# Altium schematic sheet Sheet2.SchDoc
size B
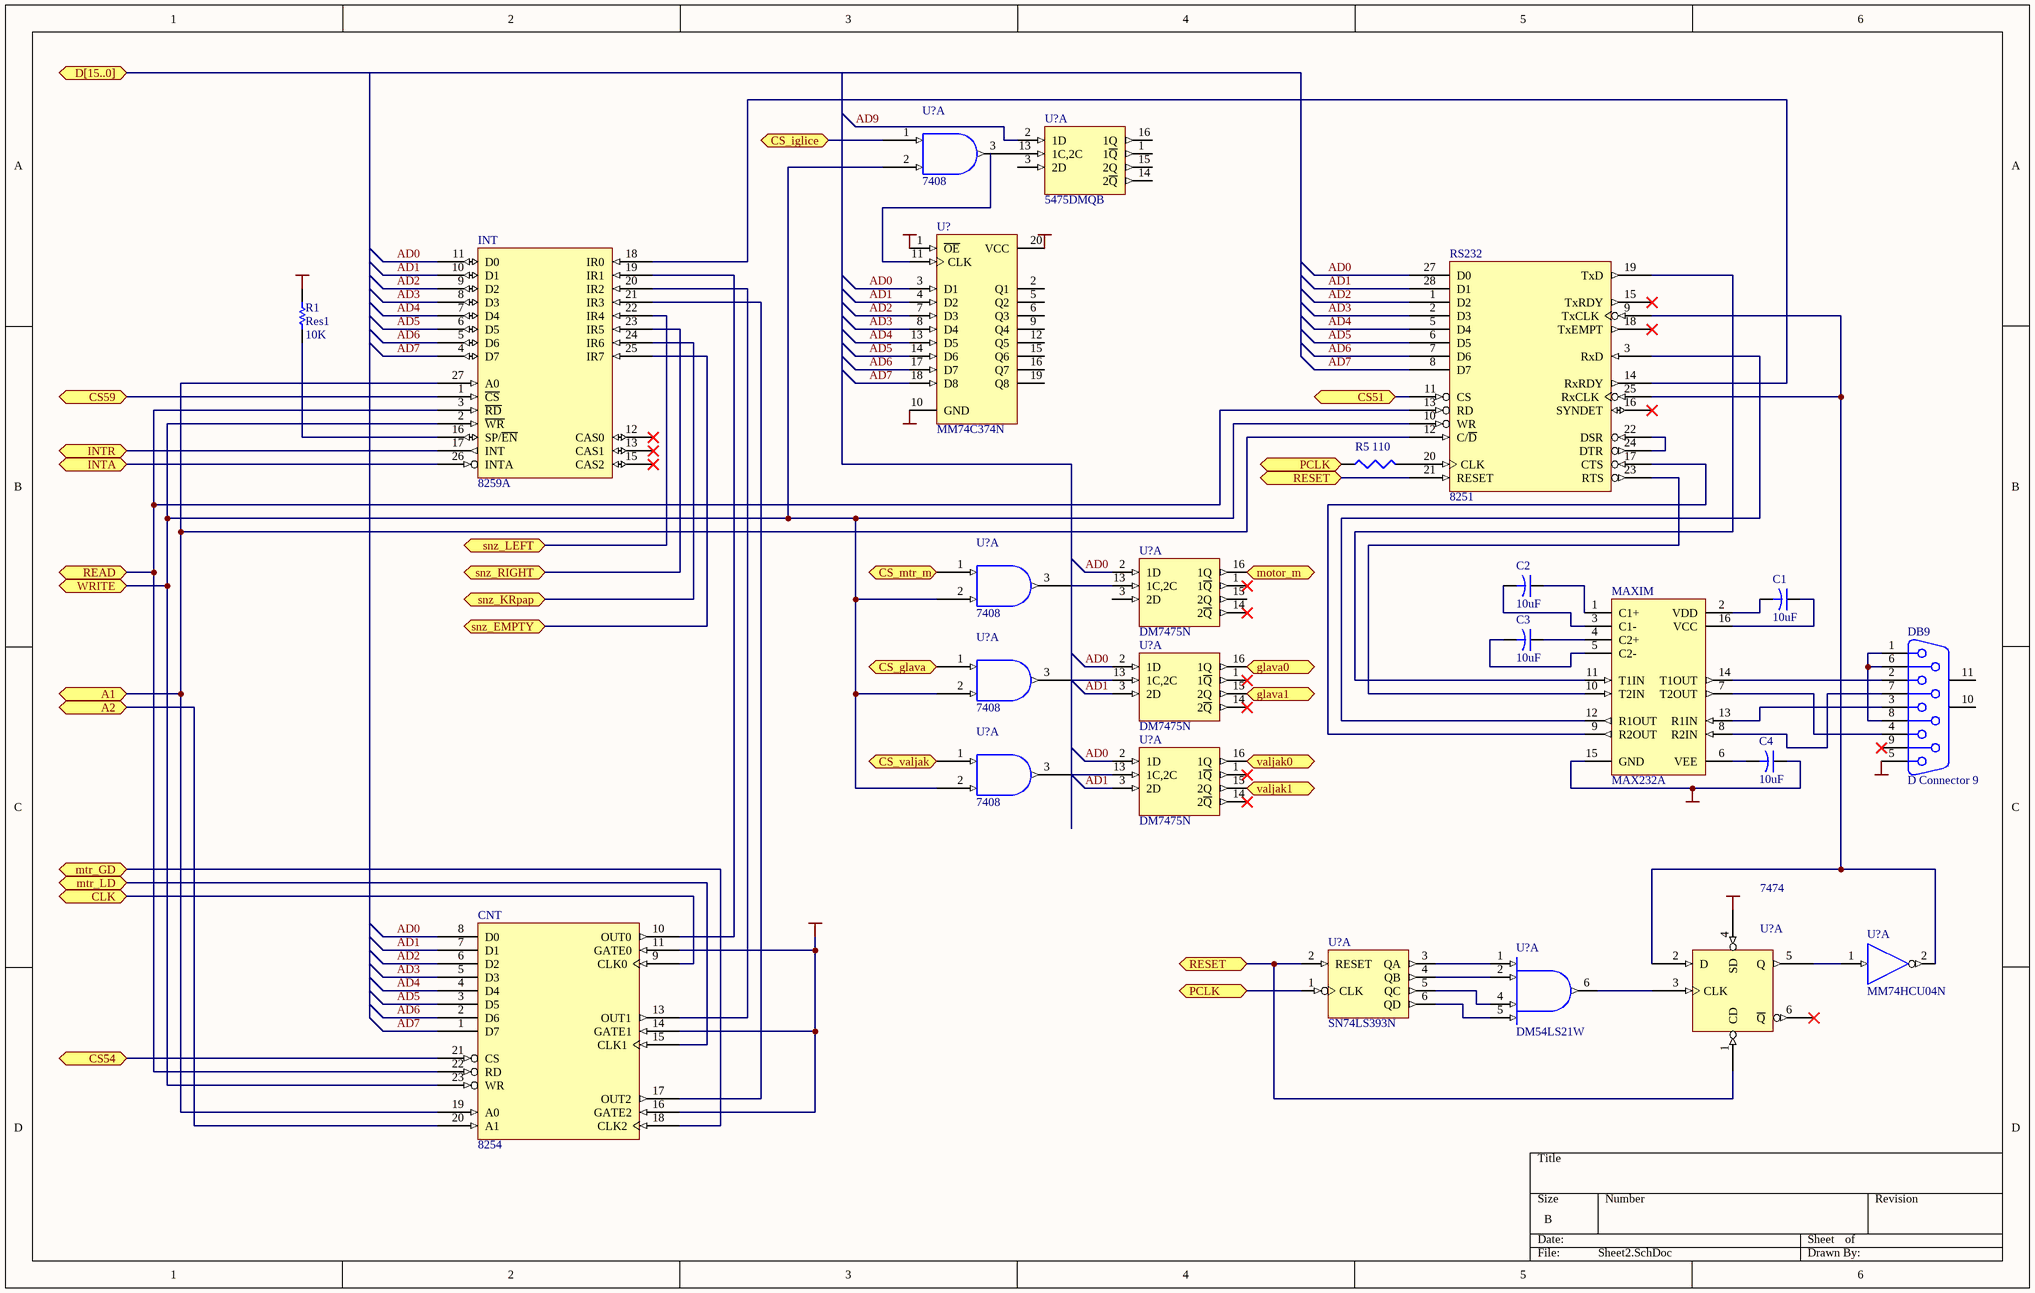
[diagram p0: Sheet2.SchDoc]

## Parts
(Parts that share a designator on the sheet are numbered #1, #2 ... from top to bottom, then left to right.)
?  R5 110
C1  10uF  [CAPR5-4X5]
C2  10uF  [CAPR5-4X5]
C3  10uF  [CAPR5-4X5]
C4  10uF  [CAPR5-4X5]
CNT  8254  [DIP24]
DB9  D Connector 9  [DSUB1.385-2H9]
INT  8259A
MAXIM  MAX232A  [SO-G16/G6.9]
R1  Res1  value 10K  [AXIAL-0.3]
RS232  8251  [DIP28]
U?#1  7408  [DIP14]  (part A of 4)
U?#2  5475DMQB  [DIP-16]  (part A of 2)
U?#3  MM74C374N  [DIP-20/E5.3]
U?#4  7408  [DIP14]  (part A of 4)
U?#5  DM7475N  [DIP-16]  (part A of 2)
U?#6  7408  [DIP14]  (part A of 4)
U?#7  DM7475N  [DIP-16]  (part A of 2)
U?#8  7408  [DIP14]  (part A of 4)
U?#9  DM7475N  [DIP-16]  (part A of 2)
U?#10  MM74HCU04N  [DIP-14/D19.7]  (part A of 6)
U?#11  SN74LS393N  [DIP-14/D19.7]  (part A of 2)
U?#12  7474  [DIP14]  (part A of 2)
U?#13  DM54LS21W  [CDFP-G14/C9.5]  (part A of 2)

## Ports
A1, A2, CLK, CS51, CS54, CS59, CS_glava, CS_iglice, CS_mtr_m, CS_valjak, D[15..0], glava0, glava1, INTA, INTR, motor_m, mtr_GD, mtr_LD, PCLK, READ, RESET, snz_EMPTY, snz_KRpap, snz_LEFT, snz_RIGHT, valjak0, valjak1, WRITE

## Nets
GND: C4.1 CNT.12(GND) DB9.5 INT.14(GND) MAXIM.15(GND) RS232.4(GND) U?#1.7(GND) U?#2.12(GND) U?#3.1(~{OE}) U?#3.10(GND) U?#4.7(GND) U?#5.12(GND) U?#6.7(GND) U?#7.12(GND) U?#8.7(GND) U?#9.12(GND) U?#10.7(GND) U?#11.7(GND) U?#12.7(GND) U?#13.7(GND)
VCC: CNT.11(GATE0) CNT.14(GATE1) CNT.16(GATE2) CNT.24(VCC) INT.28(VCC) R1.2 RS232.26(VCC) U?#1.14(VCC) U?#2.5(VCC) U?#3.20(VCC) U?#4.14(VCC) U?#5.5(VCC) U?#6.14(VCC) U?#7.5(VCC) U?#8.14(VCC) U?#9.5(VCC) U?#10.14(VCC) U?#12.4(SD) U?#12.14(VCC) U?#13.14(VCC)
VDD: U?#11.14(VDD)
A1: CNT.19(A0) INT.27(A0) RS232.12(C/~{D}) ; port A1
A2: CNT.20(A1) ; port A2
AD0: CNT.8(D0) INT.11(D0) RS232.27(D0) U?#3.3(D1) U?#5.2(1D) U?#7.2(1D) U?#9.2(1D)
AD1: CNT.7(D1) INT.10(D1) RS232.28(D1) U?#3.4(D2) U?#7.3(2D) U?#9.3(2D)
AD2: CNT.6(D2) INT.9(D2) RS232.1(D2) U?#3.7(D3)
AD3: CNT.5(D3) INT.8(D3) RS232.2(D3) U?#3.8(D4)
AD4: CNT.4(D4) INT.7(D4) RS232.5(D4) U?#3.13(D5)
AD5: CNT.3(D5) INT.6(D5) RS232.6(D5) U?#3.14(D6)
AD6: CNT.2(D6) INT.5(D6) RS232.7(D6) U?#3.17(D7)
AD7: CNT.1(D7) INT.4(D7) RS232.8(D7) U?#3.18(D8)
AD9: U?#2.2(1D)
CLK: CNT.9(CLK0) ; port CLK
CS51: RS232.11(CS) ; port CS51
CS54: CNT.21(CS) ; port CS54
CS59: INT.1(~{CS}) ; port CS59
CS_glava: U?#6.1 ; port CS_glava
CS_iglice: U?#1.1 ; port CS_iglice
CS_mtr_m: U?#4.1 ; port CS_mtr_m
CS_valjak: U?#8.1 ; port CS_valjak
glava0: U?#7.16(1Q) ; port glava0
glava1: U?#7.15(2Q) ; port glava1
INTA: INT.26(INTA) ; port INTA
INTR: INT.17(INT) ; port INTR
motor_m: U?#5.16(1Q) ; port motor_m
mtr_GD: CNT.18(CLK2) ; port mtr_GD
mtr_LD: CNT.15(CLK1) ; port mtr_LD
PCLK: ?.1 U?#11.1(CLK) ; port PCLK
READ: CNT.22(RD) INT.3(~{RD}) RS232.13(RD) ; port READ
RESET: RS232.21(RESET) U?#11.2(RESET) U?#12.1(CD) ; port RESET
snz_EMPTY: INT.25(IR7) ; port snz_EMPTY
snz_KRpap: INT.24(IR6) ; port snz_KRpap
snz_LEFT: INT.22(IR4) ; port snz_LEFT
snz_RIGHT: INT.23(IR5) ; port snz_RIGHT
valjak0: U?#9.16(1Q) ; port valjak0
valjak1: U?#9.15(2Q) ; port valjak1
WRITE: CNT.23(WR) INT.2(~{WR}) RS232.10(WR) U?#1.2 U?#4.2 U?#6.2 U?#8.2 ; port WRITE
Net?_2: ?.2 RS232.20(CLK)
NetC1_1: C1.1 MAXIM.16(VCC)
NetC1_2: C1.2 MAXIM.2(VDD)
NetC2_1: C2.1 MAXIM.1(C1+)
NetC2_2: C2.2 MAXIM.3(C1-)
NetC3_1: C3.1 MAXIM.4(C2+)
NetC3_2: C3.2 MAXIM.5(C2-)
NetC4_2: C4.2 MAXIM.6(VEE)
NetCNT_10: CNT.10(OUT0) INT.19(IR1)
NetCNT_13: CNT.13(OUT1) INT.20(IR2)
NetCNT_17: CNT.17(OUT2) INT.21(IR3)
NetDB9_1: DB9.1 DB9.6 DB9.8
NetDB9_2: DB9.2 MAXIM.14(T1OUT)
NetDB9_3: DB9.3 MAXIM.13(R1IN)
NetDB9_4: DB9.4 MAXIM.7(T2OUT)
NetDB9_7: DB9.7 MAXIM.8(R2IN)
NetINT_16: INT.16(SP/~{EN}) R1.1
NetINT_18: INT.18(IR0) RS232.14(RxRDY)
NetMAXIM_9: MAXIM.9(R2OUT) RS232.17(CTS)
NetMAXIM_10: MAXIM.10(T2IN) RS232.23(RTS)
NetMAXIM_11: MAXIM.11(T1IN) RS232.19(TxD)
NetMAXIM_12: MAXIM.12(R1OUT) RS232.3(RxD)
NetRS232_9: RS232.9(TxCLK) RS232.25(RxCLK) U?#10.2(Y) U?#12.2(D)
NetRS232_22: RS232.22(DSR) RS232.24(DTR)
NetU?#1_3: U?#1.3 U?#2.13(1C,2C)
NetU?#4_3: U?#4.3 U?#5.13(1C,2C)
NetU?#6_3: U?#6.3 U?#7.13(1C,2C)
NetU?#8_3: U?#8.3 U?#9.13(1C,2C)
NetU?#10_1: U?#10.1(A) U?#12.5(Q)
NetU?#11_3: U?#11.3(QA) U?#13.1(A)
NetU?#11_4: U?#11.4(QB) U?#13.2(B)
NetU?#11_5: U?#11.5(QC) U?#13.4(C)
NetU?#11_6: U?#11.6(QD) U?#13.5(D)
NetU?#12_3: U?#12.3(CLK) U?#13.6(Y)

Not connected (* = marked no-connect by the designer): DB9 9* 10(MH1) 11(MH2); INT 12(CAS0)* 13(CAS1)* 15(CAS2)*; RS232 15(TxRDY)* 16(SYNDET)* 18(TxEMPT)*; U?#2 1(1~{Q}) 3(2D) 14(2~{Q}) 15(2Q) 16(1Q); U?#3 2(Q1) 5(Q2) 6(Q3) 9(Q4) 11(CLK) 12(Q5) 15(Q6) 16(Q7) 19(Q8); U?#5 1(1~{Q})* 3(2D) 14(2~{Q})* 15(2Q); U?#7 1(1~{Q})* 14(2~{Q})*; U?#9 1(1~{Q})* 14(2~{Q})*; U?#12 6(~{Q})*

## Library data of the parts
? = RES1
C1-C4 = Cap2: Capacitor; Manufacturer: Generic Components; Class I: Passive
DB9 = D Connector 9: Receptacle Assembly, 9 Position, Right Angle; Manufacturer: Generic Components; Package Information: Latest Revision: O; Positions: 9
MAXIM = MAX232CWE: +5V Powered RS-232 Driver/Receiver; Manufacturer: Maxim; Class I: Communication; Class II: Transceiver
R1 = Res1: Resistor; Manufacturer: Generic Components; Class I: Passive
U?#2 = 5475DMQB: Quad Latch; Manufacturer: National Semiconductor; Class I: Logic
U?#3 = MM74C374N: Tri-State Octal D-Type Flip-Flop; Manufacturer: National Semiconductor; Class I: Logic; Class II: Latch
U?#5 U?#7 U?#9 = DM7475N: Quad Latch; Manufacturer: National Semiconductor; Class I: Logic
U?#10 = MM74HCU04N: Hex Inverter; Manufacturer: National Semiconductor; Class I: Logic; Class II: Gate
U?#11 = SN74LS393N: Dual 4-Stage Binary Counter; Manufacturer: ON Semiconductor; Class I: Logic
U?#13 = DM54LS21W: Dual 4-Input AND Gates; Manufacturer: National Semiconductor; Package Information: Latest Revision: 1990; Class I: Logic; Class II: Gate; Note: Pins 3 and 11 are NC & not drawn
